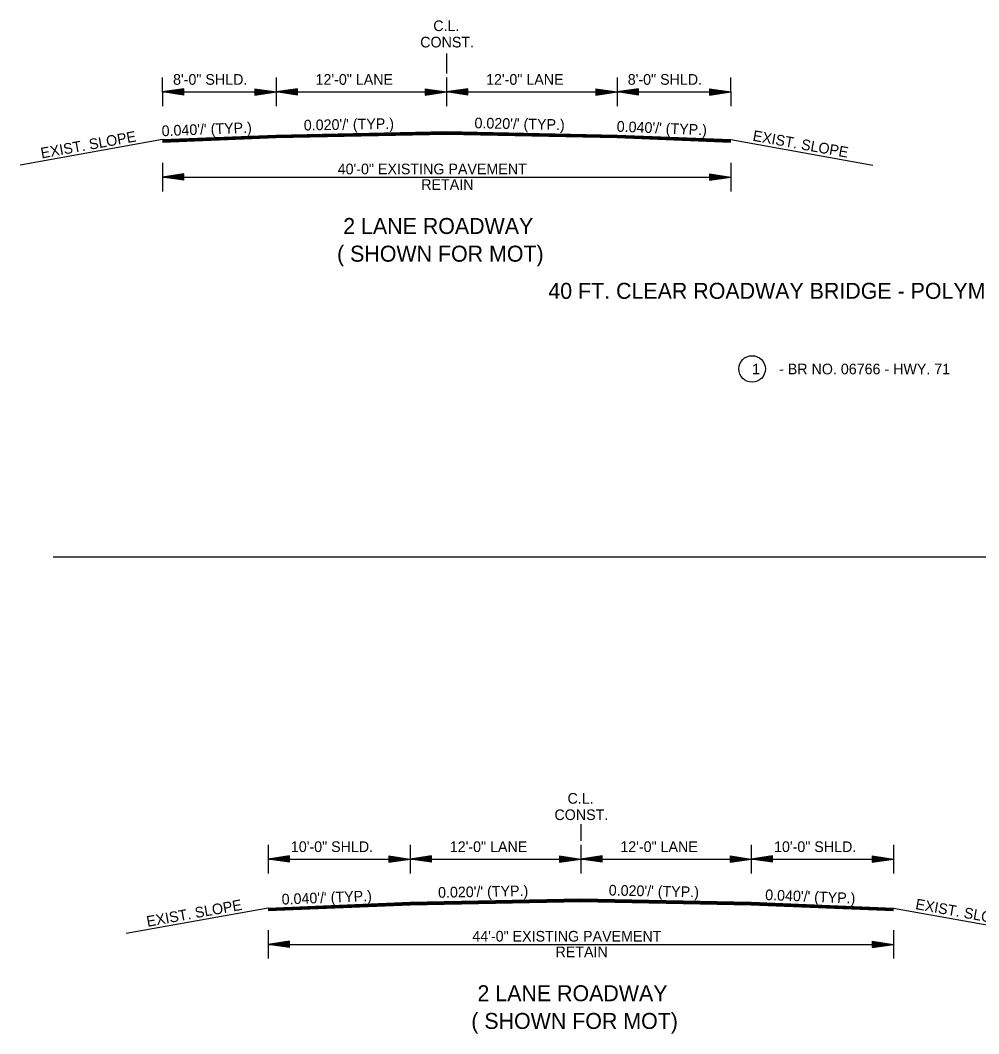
# Model space of a CAD drawing. Extents: x 550980 to 1930787, y -1972975 to 596640.
# Drawn here: x 551023 to 551697, y -1945265 to -1944552 of the extents above; entities that cross this region are included whole.
import ezdxf

# ---------------------------------------------------------------- set-up
doc = ezdxf.new("R2010")
doc.units = 0
doc.layers.add('R_Border', color=7, linetype='Continuous')
doc.layers.add('R_Draft', color=7, linetype='Continuous')

# ---------------------------------------------------------------- blocks, each defined once
blk = doc.blocks.new('ARROW')
at = {"layer": 'R_Draft'}
for p, q in [((-2, 0.3), (0, 0)), ((-2, 0.3), (-2, -0.3)), ((-2, 0.25), (-0.334, 0)), ((-2, 0.199), (-0.678, 0)), ((-2, 0.149), (-1.011, 0)), ((-2, 0.097), (-1.35, 0)), ((-2, 0.047), (-1.684, 0)), ((-2, -0.3), (0, 0)), ((-2, -0.098), (-1.35, 0)), ((-2, -0.199), (-0.678, 0)), ((-2, -0.25), (-0.334, 0)), ((-2, -0.149), (-1.011, 0)), ((-2, -0.047), (-1.684, 0))]:
    blk.add_line(p, q, dxfattribs=at)
blk = doc.blocks.new('BPPOLY')
at = {"layer": 'R_Border'}
blk.add_circle((0, 0), 9.34, dxfattribs=at)

msp = doc.modelspace()

# ---------------------------------------------------------------- linework, layer by layer
at = {"layer": 'R_Border'}
for p, q in [((551322.67, -1944575.11), (551322.67, -1944589.11)), ((551122.67, -1944602.11), (551122.67, -1944592.11)), ((551202.67, -1944592.11), (551202.67, -1944612.11)), ((551322.67, -1944592.11), (551322.67, -1944612.11)), ((551442.67, -1944592.11), (551442.67, -1944612.11)), ((551522.67, -1944602.11), (551522.67, -1944592.11)), ((551122.67, -1944602.11), (551522.67, -1944602.11)), ((551122.67, -1944602.11), (551122.67, -1944612.11)), ((551522.67, -1944602.11), (551522.67, -1944612.11)), ((551122.67, -1944635.71), (551022.67, -1944653.71)), ((551522.67, -1944635.71), (551622.67, -1944653.71)), ((551522.67, -1944635.71), (551622.67, -1944653.71)), ((551122.67, -1944652.11), (551122.67, -1944672.11)), ((551522.67, -1944652.11), (551522.67, -1944672.11)), ((551122.67, -1944662.11), (551522.67, -1944662.11)), ((551045.9, -1944929.35), (552007.39, -1944929.35)), ((551417.14, -1945117.5), (551417.14, -1945129.19)), ((551197.14, -1945132), (551197.14, -1945152)), ((551297.14, -1945132), (551297.14, -1945152)), ((551417.14, -1945132), (551417.14, -1945152)), ((551537.14, -1945132), (551537.14, -1945152)), ((551637.14, -1945132), (551637.14, -1945152)), ((551212.14, -1945139.75), (551197.14, -1945142)), ((551212.14, -1945144.25), (551212.14, -1945139.75)), ((551282.14, -1945139.75), (551297.14, -1945142)), ((551282.14, -1945139.75), (551282.14, -1945144.25)), ((551312.14, -1945139.75), (551297.14, -1945142)), ((551312.14, -1945144.25), (551312.14, -1945139.75)), ((551402.14, -1945139.75), (551417.14, -1945142)), ((551402.14, -1945139.75), (551402.14, -1945144.25)), ((551432.14, -1945139.75), (551417.14, -1945142)), ((551432.14, -1945144.25), (551432.14, -1945139.75)), ((551522.14, -1945139.75), (551537.14, -1945142)), ((551522.14, -1945139.75), (551522.14, -1945144.25)), ((551552.14, -1945139.75), (551537.14, -1945142)), ((551552.14, -1945144.25), (551552.14, -1945139.75)), ((551622.14, -1945139.75), (551637.14, -1945142)), ((551622.14, -1945139.75), (551622.14, -1945144.25)), ((551197.14, -1945142), (551637.14, -1945142)), ((551212.14, -1945144.25), (551197.14, -1945142)), ((551212.14, -1945140.12), (551199.64, -1945142)), ((551212.14, -1945143.87), (551199.64, -1945142)), ((551212.14, -1945140.5), (551202.22, -1945142)), ((551212.14, -1945143.49), (551202.22, -1945142)), ((551212.14, -1945140.88), (551204.72, -1945142)), ((551212.14, -1945143.11), (551204.72, -1945142)), ((551212.14, -1945141.26), (551207.26, -1945142)), ((551212.14, -1945142.72), (551207.26, -1945142)), ((551212.14, -1945141.64), (551209.77, -1945142)), ((551212.14, -1945142.35), (551209.77, -1945142)), ((551282.14, -1945140.12), (551294.63, -1945142)), ((551282.14, -1945140.5), (551292.05, -1945142)), ((551282.14, -1945140.88), (551289.56, -1945142)), ((551282.14, -1945141.27), (551287.01, -1945142)), ((551282.14, -1945141.64), (551284.51, -1945142)), ((551282.14, -1945144.25), (551297.14, -1945142)), ((551282.14, -1945142.73), (551287.01, -1945142)), ((551282.14, -1945143.49), (551292.05, -1945142)), ((551282.14, -1945143.87), (551294.63, -1945142)), ((551282.14, -1945143.11), (551289.56, -1945142)), ((551282.14, -1945142.35), (551284.51, -1945142)), ((551312.14, -1945144.25), (551297.14, -1945142)), ((551312.14, -1945140.12), (551299.64, -1945142)), ((551312.14, -1945143.87), (551299.64, -1945142)), ((551312.14, -1945140.5), (551302.22, -1945142)), ((551312.14, -1945143.49), (551302.22, -1945142)), ((551312.14, -1945140.88), (551304.72, -1945142)), ((551312.14, -1945143.11), (551304.72, -1945142)), ((551312.14, -1945141.26), (551307.26, -1945142)), ((551312.14, -1945142.72), (551307.26, -1945142)), ((551312.14, -1945141.64), (551309.77, -1945142)), ((551312.14, -1945142.35), (551309.77, -1945142)), ((551402.14, -1945140.12), (551414.63, -1945142)), ((551402.14, -1945140.5), (551412.05, -1945142)), ((551402.14, -1945140.88), (551409.56, -1945142)), ((551402.14, -1945141.27), (551407.01, -1945142)), ((551402.14, -1945141.64), (551404.51, -1945142)), ((551402.14, -1945144.25), (551417.14, -1945142)), ((551402.14, -1945142.73), (551407.01, -1945142)), ((551402.14, -1945143.49), (551412.05, -1945142)), ((551402.14, -1945143.87), (551414.63, -1945142)), ((551402.14, -1945143.11), (551409.56, -1945142)), ((551402.14, -1945142.35), (551404.51, -1945142)), ((551432.14, -1945144.25), (551417.14, -1945142)), ((551432.14, -1945140.12), (551419.64, -1945142)), ((551432.14, -1945143.87), (551419.64, -1945142)), ((551432.14, -1945140.5), (551422.22, -1945142)), ((551432.14, -1945143.49), (551422.22, -1945142)), ((551432.14, -1945140.88), (551424.72, -1945142)), ((551432.14, -1945143.11), (551424.72, -1945142)), ((551432.14, -1945141.26), (551427.26, -1945142)), ((551432.14, -1945142.72), (551427.26, -1945142)), ((551432.14, -1945141.64), (551429.77, -1945142)), ((551432.14, -1945142.35), (551429.77, -1945142)), ((551522.14, -1945140.12), (551534.63, -1945142)), ((551522.14, -1945140.5), (551532.05, -1945142)), ((551522.14, -1945140.88), (551529.56, -1945142)), ((551522.14, -1945141.27), (551527.01, -1945142)), ((551522.14, -1945141.64), (551524.51, -1945142)), ((551522.14, -1945144.25), (551537.14, -1945142)), ((551522.14, -1945142.73), (551527.01, -1945142)), ((551522.14, -1945143.49), (551532.05, -1945142)), ((551522.14, -1945143.87), (551534.63, -1945142)), ((551522.14, -1945143.11), (551529.56, -1945142)), ((551522.14, -1945142.35), (551524.51, -1945142)), ((551552.14, -1945144.25), (551537.14, -1945142)), ((551552.14, -1945140.12), (551539.64, -1945142)), ((551552.14, -1945143.87), (551539.64, -1945142)), ((551552.14, -1945140.5), (551542.22, -1945142)), ((551552.14, -1945143.49), (551542.22, -1945142)), ((551552.14, -1945140.88), (551544.72, -1945142)), ((551552.14, -1945143.11), (551544.72, -1945142)), ((551552.14, -1945141.26), (551547.26, -1945142)), ((551552.14, -1945142.72), (551547.26, -1945142)), ((551552.14, -1945141.64), (551549.77, -1945142)), ((551552.14, -1945142.35), (551549.77, -1945142)), ((551622.14, -1945140.12), (551634.63, -1945142)), ((551622.14, -1945140.5), (551632.05, -1945142)), ((551622.14, -1945140.88), (551629.56, -1945142)), ((551622.14, -1945141.27), (551627.01, -1945142)), ((551622.14, -1945141.64), (551624.51, -1945142)), ((551622.14, -1945144.25), (551637.14, -1945142)), ((551622.14, -1945142.73), (551627.01, -1945142)), ((551622.14, -1945143.49), (551632.05, -1945142)), ((551622.14, -1945143.87), (551634.63, -1945142)), ((551622.14, -1945143.11), (551629.56, -1945142)), ((551622.14, -1945142.35), (551624.51, -1945142)), ((551197.14, -1945176.4), (551097.14, -1945194.4)), ((551637.14, -1945176.4), (551737.14, -1945194.4)), ((551197.14, -1945192), (551197.14, -1945212)), ((551637.14, -1945192), (551637.14, -1945212)), ((551212.14, -1945199.75), (551197.14, -1945202)), ((551197.14, -1945202), (551637.14, -1945202)), ((551212.14, -1945204.25), (551197.14, -1945202)), ((551212.14, -1945200.12), (551199.64, -1945202)), ((551212.14, -1945203.87), (551199.64, -1945202)), ((551212.14, -1945200.5), (551202.22, -1945202)), ((551212.14, -1945203.49), (551202.22, -1945202)), ((551212.14, -1945200.88), (551204.72, -1945202)), ((551212.14, -1945203.11), (551204.72, -1945202)), ((551212.14, -1945201.26), (551207.26, -1945202)), ((551212.14, -1945202.72), (551207.26, -1945202)), ((551212.14, -1945201.64), (551209.77, -1945202)), ((551212.14, -1945202.35), (551209.77, -1945202)), ((551212.14, -1945204.25), (551212.14, -1945199.75)), ((551622.14, -1945199.75), (551637.14, -1945202)), ((551622.14, -1945199.75), (551622.14, -1945204.25)), ((551622.14, -1945200.12), (551634.63, -1945202)), ((551622.14, -1945200.5), (551632.05, -1945202)), ((551622.14, -1945200.88), (551629.56, -1945202)), ((551622.14, -1945201.27), (551627.01, -1945202)), ((551622.14, -1945201.64), (551624.51, -1945202)), ((551622.14, -1945204.25), (551637.14, -1945202)), ((551622.14, -1945202.73), (551627.01, -1945202)), ((551622.14, -1945203.49), (551632.05, -1945202)), ((551622.14, -1945203.87), (551634.63, -1945202)), ((551622.14, -1945203.11), (551629.56, -1945202)), ((551622.14, -1945202.35), (551624.51, -1945202))]:
    msp.add_line(p, q, dxfattribs=at)
for points in [[(551122.67, -1944635.71), (551202.67, -1944632.51), (551322.67, -1944630.11), (551442.67, -1944632.51), (551522.67, -1944635.71)], [(551122.67, -1944636.01), (551202.67, -1944632.81), (551322.67, -1944630.41), (551442.67, -1944632.81), (551522.67, -1944636.01)], [(551122.67, -1944636.31), (551202.67, -1944633.11), (551322.67, -1944630.71), (551442.67, -1944633.11), (551522.67, -1944636.31)], [(551122.67, -1944636.61), (551202.67, -1944633.41), (551322.67, -1944631.01), (551442.67, -1944633.41), (551522.67, -1944636.61)], [(551122.67, -1944636.91), (551202.67, -1944633.71), (551322.67, -1944631.31), (551442.67, -1944633.71), (551522.67, -1944636.91)], [(551122.67, -1944637.21), (551202.67, -1944634.01), (551322.67, -1944631.61), (551442.67, -1944634.01), (551522.67, -1944637.21)], [(551122.67, -1944637.51), (551202.67, -1944634.31), (551322.67, -1944631.91), (551442.67, -1944634.31), (551522.67, -1944637.51)], [(551197.14, -1945176.4), (551297.14, -1945172.4), (551417.14, -1945170), (551537.14, -1945172.4), (551637.14, -1945176.4)], [(551197.14, -1945176.7), (551297.14, -1945172.7), (551417.14, -1945170.3), (551537.14, -1945172.7), (551637.14, -1945176.7)], [(551197.14, -1945177), (551297.14, -1945173), (551417.14, -1945170.6), (551537.14, -1945173), (551637.14, -1945177)], [(551197.14, -1945177.3), (551297.14, -1945173.3), (551417.14, -1945170.9), (551537.14, -1945173.3), (551637.14, -1945177.3)], [(551197.14, -1945177.6), (551297.14, -1945173.6), (551417.14, -1945171.2), (551537.14, -1945173.6), (551637.14, -1945177.6)], [(551197.14, -1945177.9), (551297.14, -1945173.9), (551417.14, -1945171.5), (551537.14, -1945173.9), (551637.14, -1945177.9)], [(551197.14, -1945178.2), (551297.14, -1945174.2), (551417.14, -1945171.8), (551537.14, -1945174.2), (551637.14, -1945178.2)]]:
    msp.add_lwpolyline(points, dxfattribs=at)

# ---------------------------------------------------------------- block references
at = {"layer": 'R_Border', "xscale": 7.5, "yscale": 7.5, "rotation": 180}
for p in [(551122.67, -1944602.11), (551202.67, -1944602.11), (551322.67, -1944602.11), (551442.67, -1944602.11), (551122.67, -1944662.11)]:
    msp.add_blockref('ARROW', p, dxfattribs=at)
at = {"layer": 'R_Border', "xscale": 7.5, "yscale": 7.5}
for p in [(551202.67, -1944602.11), (551322.67, -1944602.11), (551442.67, -1944602.11), (551522.67, -1944602.11), (551522.67, -1944662.11)]:
    msp.add_blockref('ARROW', p, dxfattribs=at)
at = {"layer": 'R_Border'}
msp.add_blockref('BPPOLY', (551537.67, -1944797.11), dxfattribs=at)

# ---------------------------------------------------------------- texts
for s, height, p in [('C.L.', 7.5, (551313.34, -1944559.34)), ('CONST.', 7.5, (551304.13, -1944570.84)), ('8\'-0" SHLD.', 7.5, (551130.19, -1944597.11)), ('12\'-0" LANE', 7.5, (551230.48, -1944597.11)), ('12\'-0" LANE', 7.5, (551350.48, -1944597.11)), ('8\'-0" SHLD.', 7.5, (551450.19, -1944597.11)), ('40\'-0" EXISTING PAVEMENT', 7.5, (551246.05, -1944660.11)), ('RETAIN', 7.5, (551304.86, -1944671.11)), ('2 LANE ROADWAY', 11.25, (551249.94, -1944702.11)), ('( SHOWN FOR MOT)', 11.25, (551245.6, -1944721.59)), ('40 FT. CLEAR ROADWAY BRIDGE - POLYMER OVERLAY', 11.25, (551394.3, -1944747.74)), ('1', 7.5, (551537.67, -1944800.86)), ('- BR NO. 06766 - HWY. 71', 7.5, (551556.67, -1944800.86)), ('C.L.', 7.5, (551407.81, -1945103)), ('CONST.', 7.5, (551398.59, -1945114.5)), ('10\'-0" SHLD.', 7.5, (551213.12, -1945137)), ('12\'-0" LANE', 7.5, (551324.95, -1945137)), ('12\'-0" LANE', 7.5, (551444.95, -1945137)), ('10\'-0" SHLD.', 7.5, (551553.12, -1945137)), ('44\'-0" EXISTING PAVEMENT', 7.5, (551340.81, -1945200)), ('RETAIN', 7.5, (551399.33, -1945211)), ('2 LANE ROADWAY', 11.25, (551344.41, -1945242)), ('( SHOWN FOR MOT)', 11.25, (551340.07, -1945261.48))]:
    msp.add_text(s, height=height, dxfattribs=at).set_placement(p)
for s, rotation, p in [("0.040'/' (TYP.)", 2.2916, (551122.31, -1944633.33)), ("0.020'/' (TYP.)", 1.1458, (551222.28, -1944629.32)), ("0.020'/' (TYP.)", 358.8542, (551342.28, -1944627.7)), ("0.040'/' (TYP.)", 357.7084, (551442.31, -1944630.1)), ('EXIST. SLOPE', 10.204, (551037.74, -1944649)), ('EXIST. SLOPE', 349.796, (551537.74, -1944636.43)), ("0.020'/' (TYP.)", 1.1458, (551316.75, -1945169.2)), ("0.020'/' (TYP.)", 358.8542, (551436.75, -1945167.59)), ("0.040'/' (TYP.)", 2.2916, (551206.78, -1945174.01)), ("0.040'/' (TYP.)", 357.7084, (551546.78, -1945170.78)), ('EXIST. SLOPE', 10.204, (551112.21, -1945189.68)), ('EXIST. SLOPE', 349.796, (551652.21, -1945177.11))]:
    msp.add_text(s, height=7.5, rotation=rotation, dxfattribs=at).set_placement(p)

doc.saveas('drawing.dxf')
